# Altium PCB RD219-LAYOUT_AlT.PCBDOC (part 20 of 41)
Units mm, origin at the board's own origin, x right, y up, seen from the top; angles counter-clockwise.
Board outline 209.75 x 159.97 mm, 2 copper layers (TOP, BOTTOM), stack 0 mm thick; 398 components, 199 nets, 1469 pads, 0 vias.
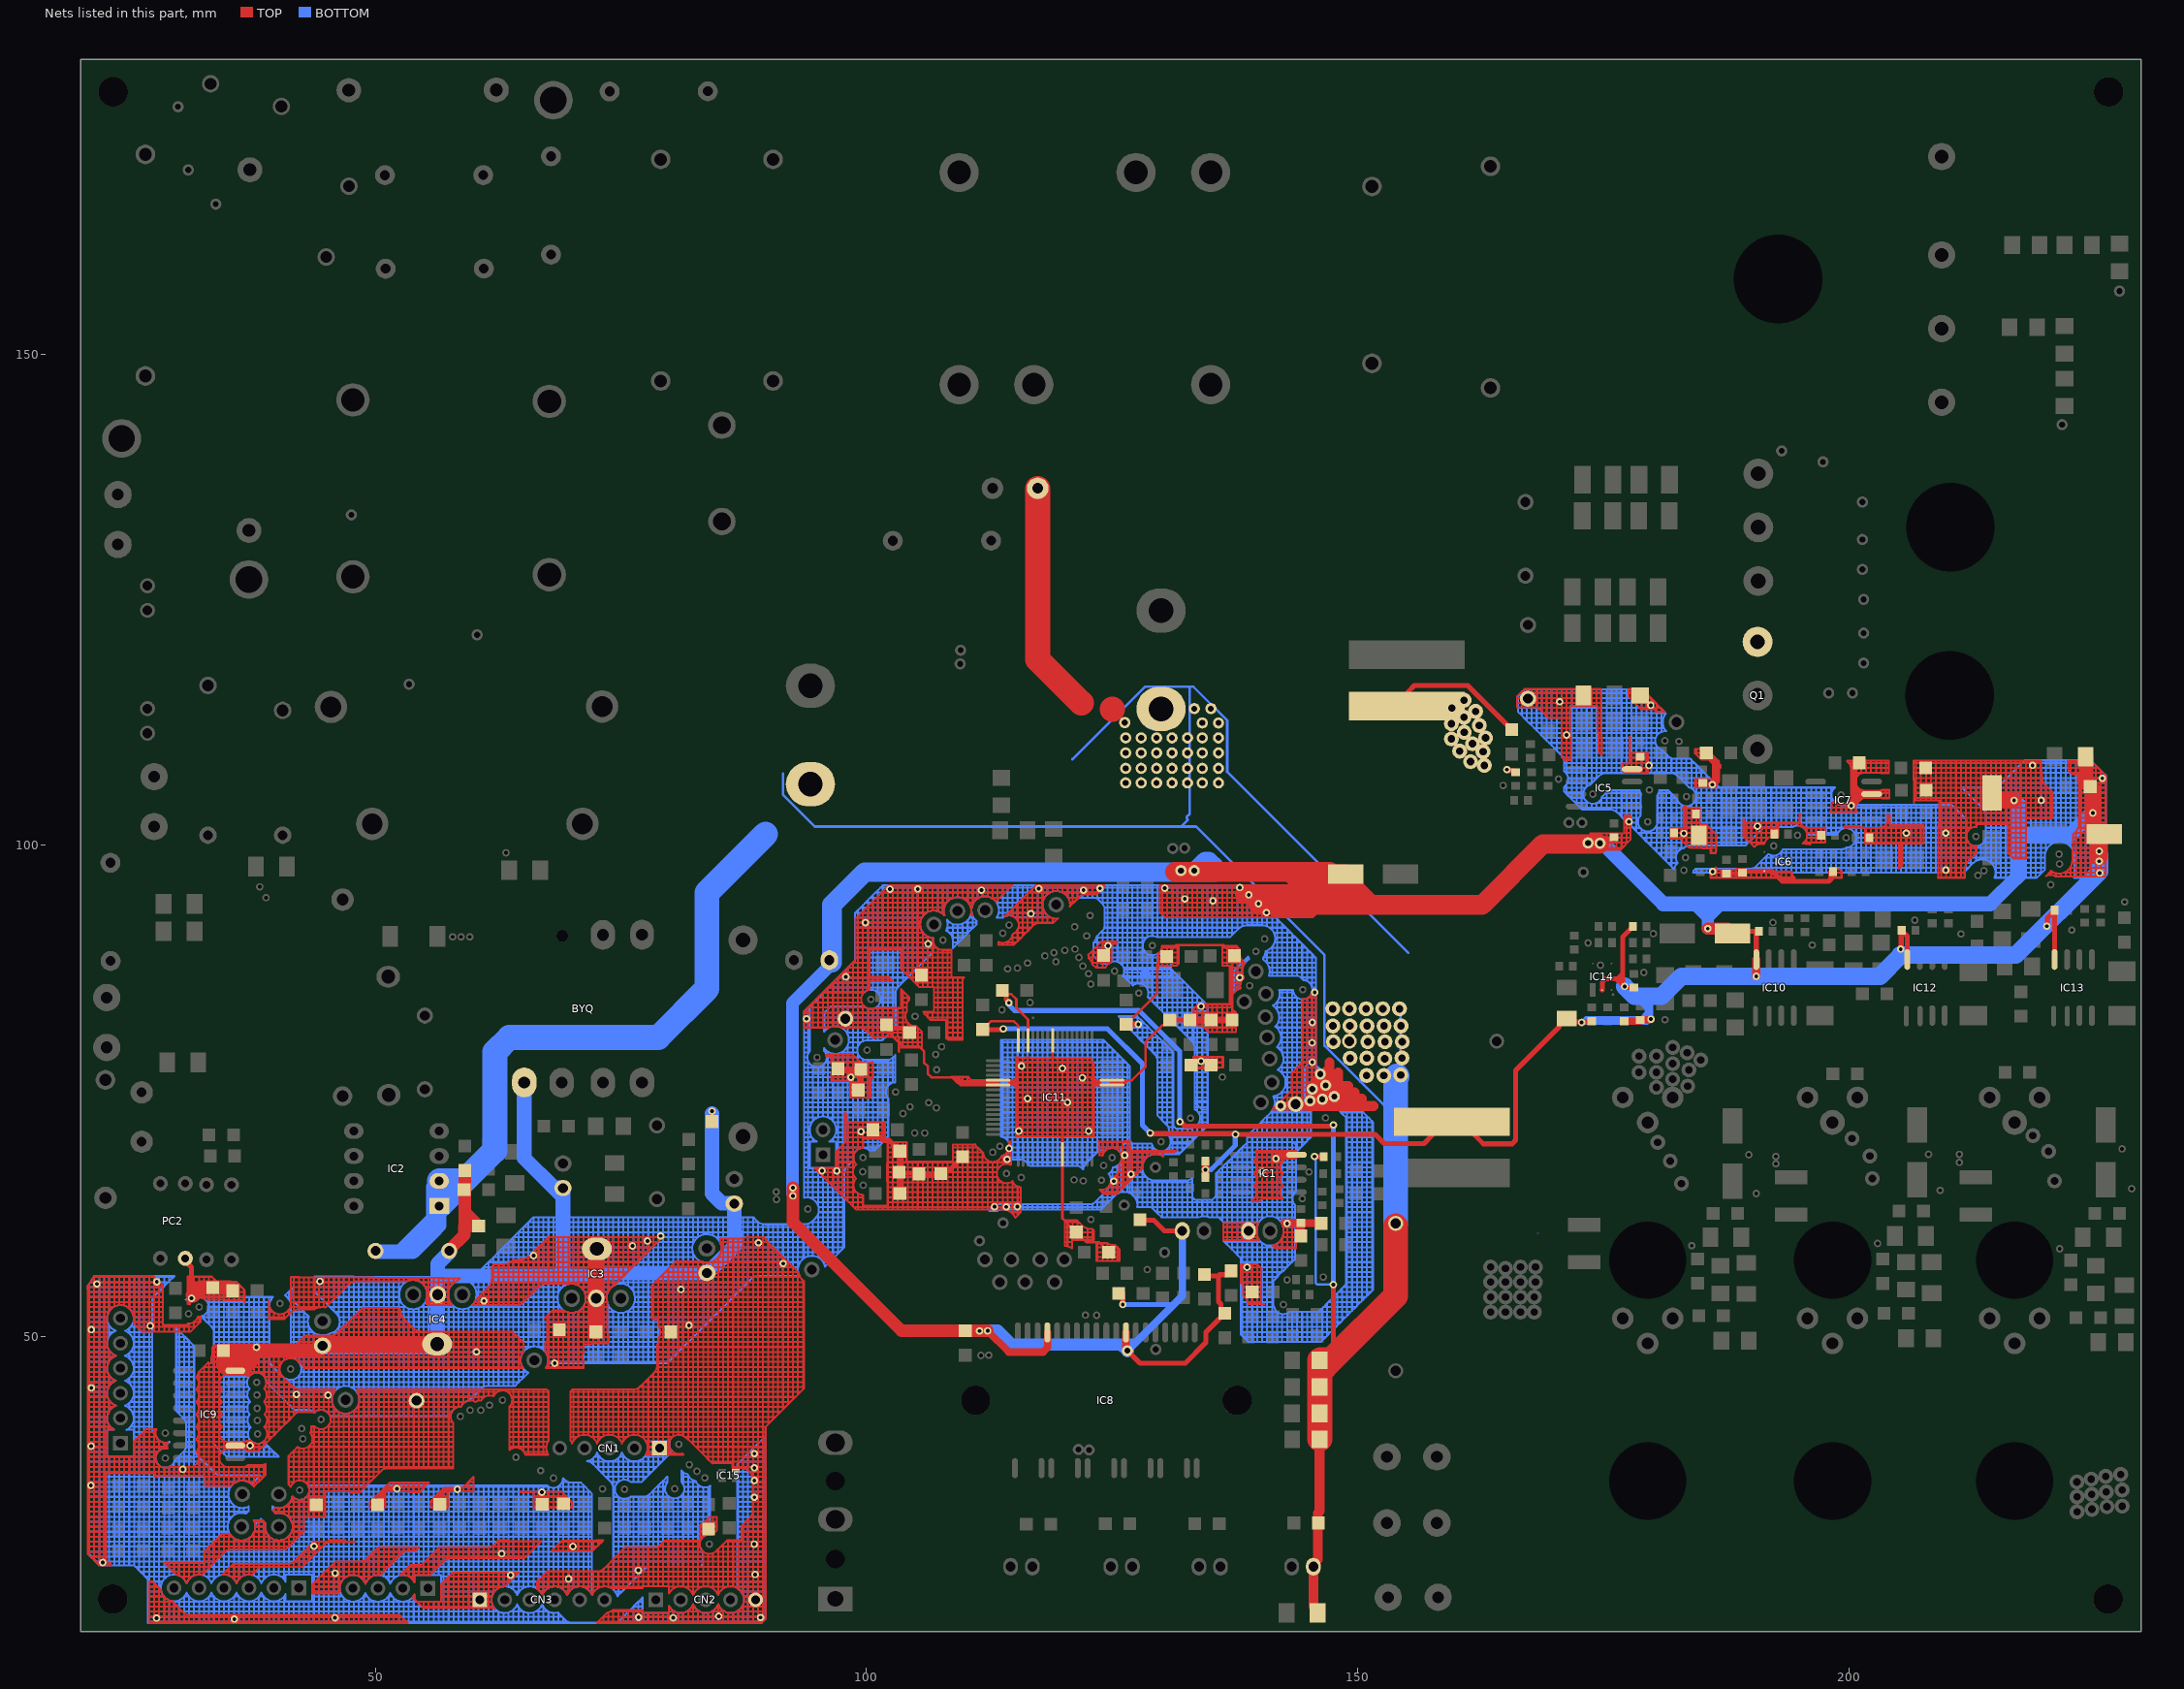
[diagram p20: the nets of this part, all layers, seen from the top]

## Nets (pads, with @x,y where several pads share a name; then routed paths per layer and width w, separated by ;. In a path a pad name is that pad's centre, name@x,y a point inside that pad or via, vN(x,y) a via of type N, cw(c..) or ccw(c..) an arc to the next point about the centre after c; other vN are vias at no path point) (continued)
GND: (continued)
  BOTTOM w0.203: pad.@22.413,27.112 22.921,27.112 ; 22.413,27.62 22.413,28.128 ; 22.413,27.62 22.921,27.62 ; 22.413,28.128 22.413,28.636 ; 22.413,28.128 22.921,28.128 ; 22.413,28.636 22.413,29.144 ; 22.413,28.636 22.921,28.636 ; 22.413,29.144 22.413,29.652 ; 22.413,29.144 22.921,29.144 ; 22.413,29.652 22.413,30.16 ; 22.413,29.652 22.921,29.652 ; 22.413,30.16 22.413,30.668 ; 22.413,30.16 22.921,30.16 ; 22.413,30.668 22.413,31.176 ; 22.413,30.668 22.921,30.668 ; 22.413,31.176 22.413,31.684 ; 22.413,31.176 22.921,31.176 ; 22.413,31.684 22.413,32.192 ; 22.413,31.684 22.921,31.684 ; 22.413,32.192 22.413,32.7 ; 22.413,32.192 22.921,32.192 ; 22.413,32.7 22.413,33.208 ; 22.413,32.7 22.921,32.7 ; 22.413,33.208 22.413,33.716 ; 22.413,33.208 22.921,33.208 ; 22.413,33.716 22.413,34.224 ; 22.413,33.716 22.921,33.716 ; 22.413,34.224 22.413,34.732 ; 22.413,34.224 22.921,34.224 ; 22.413,34.732 22.413,35.24 ; 22.413,34.732 22.921,34.732 ; 22.413,35.24 22.413,35.748 ; 22.413,35.24 22.921,35.24 ; 22.413,35.748 22.413,36.256 ; 22.413,35.748 22.921,35.748 ; 22.413,36.256 22.921,36.256 ; 22.413,36.256 22.413,36.764 ; 22.413,36.764 22.413,37.272 ; 22.413,36.764 22.921,36.764 ; 22.413,37.272 22.413,37.78 ; 22.413,37.272 22.921,37.272 ; 22.413,37.78 22.413,38.288 ; 22.413,37.78 22.921,37.78 ; 22.413,38.288 22.413,38.796 ; 22.413,38.288 22.712,38.288 ; 22.413,38.796 22.413,39.304 ; 22.413,38.796 22.712,38.796 ; 22.413,39.304 22.413,39.812 ; 22.413,39.304 22.712,39.304 ; 22.413,39.812 22.413,40.32 ; 22.413,39.812 22.712,39.812 ; 22.413,40.32 22.413,40.828 ; 22.413,40.32 22.712,40.32 ; 22.413,40.828 22.413,41.336 ; 22.413,40.828 22.921,40.828 ; 22.413,41.336 22.413,41.844 ; 22.413,41.336 22.767,41.336 ; 22.413,41.844 22.413,42.352 ; 22.413,41.844 22.718,41.844 ; 22.413,42.352 22.413,42.86 ; 22.413,42.352 22.871,42.352 ; 22.413,42.86 22.413,43.368 ; 22.413,42.86 22.921,42.86 ; 22.413,43.368 22.413,43.876 ; 22.413,43.368 22.921,43.368 ; 22.413,43.876 22.413,44.384 ; 22.413,43.876 22.767,43.876 ; 22.413,44.384 22.413,44.892 ; 22.413,44.384 22.718,44.384 ; 22.413,44.892 22.413,45.4 ; 22.413,44.892 22.871,44.892 ; 22.413,45.4 22.413,45.908 ; 22.413,45.4 22.921,45.4 ; 22.413,45.908 22.413,46.416 ; 22.413,45.908 22.921,45.908 ; 22.413,46.416 22.413,46.924 ; 22.413,46.416 22.767,46.416 ; 22.413,46.924 22.413,47.432 ; 22.413,46.924 22.718,46.924 ; 22.413,47.432 22.413,47.94 ; 22.413,47.432 22.871,47.432 ; 22.413,47.94 22.413,48.448 ; 22.413,47.94 22.921,47.94 ; 22.413,48.448 22.413,48.956 ; 22.413,48.448 22.921,48.448 ; 22.413,48.956 22.413,49.464 ; 22.413,48.956 22.767,48.956 ; 22.413,49.464 22.413,49.972 ; 22.413,49.464 22.718,49.464 ; 22.413,49.972 22.413,50.48 ; 22.413,49.972 22.871,49.972 ; 22.413,50.48 22.413,50.988 ; 22.413,50.48 22.921,50.48 ; 22.413,50.988 22.413,51.496 ; 22.413,50.988 22.921,50.988 ; 22.413,51.496 22.413,52.004 ; 22.413,51.496 22.767,51.496 ; 22.413,52.004 22.413,52.512 ; 22.413,52.004 22.718,52.004 ; 22.413,52.512 22.413,53.02 ; 22.413,52.512 22.871,52.512 ; 22.413,53.02 22.413,53.528 ; 22.413,53.02 22.921,53.02 ; 22.413,53.528 22.413,54.036 ; 22.413,53.528 22.921,53.528 ; 22.413,54.036 22.413,54.544 ; 22.413,54.036 22.921,54.036 ; 22.413,54.544 22.413,55.052 ; 22.413,54.544 22.921,54.544 ; 22.413,55.052 22.921,55.052 ; 22.413,55.052 22.413,55.56 ; 22.413,55.56 22.413,56.068 ; 22.413,55.56 22.921,55.56 ; 22.413,56.068 22.413,56.192 ; 22.413,56.068 22.921,56.068 ; 22.413,56.192 22.921,56.19 ; 22.712,38.288 22.712,38.796 ; 22.712,38.288 22.712,37.825 22.921,37.825 ; 22.712,38.796 22.712,39.304 ; 22.712,39.304 22.712,39.812 ; 22.712,39.812 22.712,40.32 ; 22.712,40.32 22.712,40.529 22.921,40.529 ; 22.718,41.844 ccw(c24.064,41.717) 22.718,41.835 ccw(c24.064,41.717) 22.767,41.336 ; 22.718,41.844 cw(c24.064,41.717) 22.871,42.352 ; 22.718,44.384 ccw(c24.064,44.257) 22.718,44.375 ccw(c24.064,44.257) 22.767,43.876 ; 22.718,44.384 cw(c24.064,44.257) 22.871,44.892 ; 22.718,46.924 ccw(c24.064,46.797) 22.718,46.915 ccw(c24.064,46.797) 22.767,46.416 ; 22.718,46.924 cw(c24.064,46.797) 22.871,47.432 ; 22.718,49.464 ccw(c24.064,49.337) 22.718,49.455 ccw(c24.064,49.337) 22.767,48.956 ; 22.718,49.464 cw(c24.064,49.337) 22.871,49.972 ; 22.718,52.004 ccw(c24.064,51.877) 22.718,51.995 ccw(c24.064,51.877) 22.767,51.496 ; 22.718,52.004 cw(c24.064,51.877) 22.871,52.512 ; 22.767,41.336 ccw(c24.064,41.717) 22.918,41.001 ccw(c24.064,41.717) 22.921,40.996 ; 22.767,43.876 ccw(c24.064,44.257) 22.918,43.541 ccw(c24.064,44.257) 22.921,43.536 ; 22.767,46.416 ccw(c24.064,46.797) 22.918,46.081 ccw(c24.064,46.797) 22.921,46.076 ; 22.767,48.956 ccw(c24.064,49.337) 22.918,48.621 ccw(c24.064,49.337) 22.921,48.616 ; 22.767,51.496 ccw(c24.064,51.877) 22.918,51.161 ccw(c24.064,51.877) 22.921,51.156 ; 22.871,42.352 cw(c24.064,41.717) 22.918,42.433 cw(c24.064,41.717) 22.921,42.438 ; 22.871,44.892 cw(c24.064,44.257) 22.918,44.973 cw(c24.064,44.257) 22.921,44.978 ; 22.871,47.432 cw(c24.064,46.797) 22.918,47.513 cw(c24.064,46.797) 22.921,47.518 ; 22.871,49.972 cw(c24.064,49.337) 22.918,50.053 cw(c24.064,49.337) 22.921,50.058 ; 22.921,26.731 22.921,27.112 ; 22.921,26.731 23.429,26.731 ; 22.921,27.112 22.921,27.62 ; 22.921,27.112 23.429,27.112 ; 22.921,27.62 22.921,28.128 ; 22.921,27.62 23.429,27.62 ; 22.921,28.128 22.921,28.636 ; 22.921,28.128 23.429,28.128 ; 22.921,28.636 22.921,29.144 ; 22.921,28.636 23.429,28.636 ; 22.921,29.144 22.921,29.652 ; 22.921,29.144 23.429,29.144 ; 22.921,29.652 22.921,30.16 ; 22.921,29.652 23.429,29.652 ; 22.921,30.16 22.921,30.668 ; 22.921,30.16 23.429,30.16 ; 22.921,30.668 22.921,31.176 ; 22.921,30.668 23.429,30.668 ; 22.921,31.176 22.921,31.684 ; 22.921,31.176 23.429,31.176 ; 22.921,31.684 22.921,32.192 ; 22.921,31.684 23.429,31.684 ; 22.921,32.192 22.921,32.7 ; 22.921,32.192 23.429,32.192 ; 22.921,32.7 22.921,33.208 ; 22.921,32.7 23.429,32.7 ; 22.921,33.208 22.921,33.716 ; 22.921,33.208 23.429,33.208 ; 22.921,33.716 22.921,34.224 ; 22.921,33.716 23.429,33.716 ; 22.921,34.224 22.921,34.732 ; 22.921,34.224 23.429,34.224 ; 22.921,34.732 22.921,35.24 ; 22.921,34.732 23.429,34.732 ; 22.921,35.24 22.921,35.748 ; 22.921,35.24 23.429,35.24 ; 22.921,35.748 22.921,36.256 ; 22.921,35.748 23.429,35.748 ; 22.921,36.256 22.921,36.764 ; 22.921,36.256 23.429,36.256 ; 22.921,36.764 22.921,37.272 ; 22.921,36.764 23.429,36.764 ; 22.921,37.272 22.921,37.78 ; 22.921,37.272 23.429,37.272 ; 22.921,37.78 22.921,37.825 ; 22.921,37.78 23.429,37.78 ; 22.921,37.825 23.429,37.825 ; 22.921,40.529 22.921,40.828 ; 22.921,40.828 22.921,40.996 ; 22.921,40.828 23.046,40.828 ; 22.921,40.996 ccw(c24.064,41.717) 23.044,40.83 ccw(c24.064,41.717) 23.046,40.828 ; 22.921,42.438 cw(c24.064,41.717) 23.343,42.86 ; 22.921,42.438 22.921,42.86 ; 22.921,42.86 22.921,43.368 ; 22.921,42.86 23.343,42.86 ; 22.921,43.368 23.046,43.368 ; 22.921,43.368 22.921,43.536 ; 22.921,43.536 ccw(c24.064,44.257) 23.044,43.37 ccw(c24.064,44.257) 23.046,43.368 ; 22.921,44.978 cw(c24.064,44.257) 23.343,45.4 ; 22.921,44.978 22.921,45.4 ; 22.921,45.4 22.921,45.908 ; 22.921,45.4 23.343,45.4 ; 22.921,45.908 22.921,46.076 ; 22.921,45.908 23.046,45.908 ; 22.921,46.076 ccw(c24.064,46.797) 23.044,45.91 ccw(c24.064,46.797) 23.046,45.908 ; 22.921,47.518 cw(c24.064,46.797) 23.343,47.94 ; 22.921,47.518 22.921,47.94 ; 22.921,47.94 22.921,48.448 ; 22.921,47.94 23.343,47.94 ; 22.921,48.448 22.921,48.616 ; 22.921,48.448 23.046,48.448 ; 22.921,48.616 ccw(c24.064,49.337) 23.044,48.45 ccw(c24.064,49.337) 23.046,48.448 ; 22.921,50.058 cw(c24.064,49.337) 23.343,50.48 ; 22.921,50.058 22.921,50.48 ; 22.921,50.48 22.921,50.988 ; 22.921,50.48 23.343,50.48 ; 22.921,50.988 23.046,50.988 ; 22.921,50.988 22.921,51.156 ; 22.921,51.156 ccw(c24.064,51.877) 23.046,50.988 ; 22.921,53.02 22.921,53.528 ; 22.921,53.02 23.343,53.02 ; 22.921,53.528 22.921,54.036 ; 22.921,53.528 23.429,53.528 ; 22.921,54.036 22.921,54.544 ; 22.921,54.036 23.429,54.036 ; 22.921,54.544 22.921,55.052 ; 22.921,54.544 23.429,54.544 ; 22.921,55.052 22.921,55.56 ; 22.921,55.052 23.429,55.052 ; 22.921,55.56 22.921,56.068 ; 22.921,55.56 23.429,55.56 ; 22.921,56.068 22.921,56.19 ; 22.921,56.068 23.429,56.068 ; 22.921,56.19 23.429,56.188 ; 23.046,43.368 ccw(c24.064,44.257) 23.429,43.064 ; 23.046,45.908 ccw(c24.064,46.797) 23.429,45.604 ; 23.046,48.448 ccw(c24.064,49.337) 23.429,48.144 ; 23.046,50.988 ccw(c24.064,51.877) 23.429,50.684 ; 23.343,42.86 cw(c24.064,41.717) 23.429,42.91 ; 23.343,45.4 cw(c24.064,44.257) 23.429,45.45 ; 23.343,47.94 cw(c24.064,46.797) 23.429,47.99 ; 23.343,50.48 cw(c24.064,49.337) 23.429,50.53 ; 23.343,53.02 cw(c24.064,51.877) 23.348,53.023 cw(c24.064,51.877) 23.429,53.07 ; 23.429,26.731 23.429,27.112 ; 23.429,26.731 23.937,26.731 ; 23.429,27.112 23.429,27.62 ; 23.429,27.112 23.937,27.112 ; 23.429,27.62 23.429,28.128 ; 23.429,27.62 23.937,27.62 ; 23.429,28.128 23.429,28.636 ; 23.429,28.128 23.937,28.128 ; 23.429,28.636 23.429,29.144 ; 23.429,28.636 23.937,28.636 ; 23.429,29.144 23.429,29.652 ; 23.429,29.144 23.937,29.144 ; 23.429,29.652 23.429,30.16 ; 23.429,29.652 23.937,29.652 ; 23.429,30.16 23.429,30.668 ; 23.429,30.16 23.937,30.16 ; 23.429,30.668 23.429,31.176 ; 23.429,30.668 23.937,30.668 ; 23.429,31.176 23.429,31.684 ; 23.429,31.176 23.937,31.176 ; 23.429,31.684 23.429,32.192 ; 23.429,31.684 23.937,31.684 ; 23.429,32.192 23.429,32.7 ; 23.429,32.192 23.937,32.192 ; 23.429,32.7 23.429,33.208 ; 23.429,32.7 23.937,32.7 ; 23.429,33.208 23.429,33.716 ; 23.429,33.208 23.937,33.208 ; 23.429,33.716 23.429,34.224 ; 23.429,33.716 23.937,33.716 ; 23.429,34.224 23.429,34.732 ; 23.429,34.224 23.937,34.224 ; 23.429,34.732 23.429,35.24 ; 23.429,34.732 23.937,34.732 ; 23.429,35.24 23.429,35.748 ; 23.429,35.24 23.937,35.24 ; 23.429,35.748 23.429,36.256 ; 23.429,35.748 23.937,35.748 ; 23.429,36.256 23.429,36.764 ; 23.429,36.256 23.937,36.256 ; 23.429,36.764 23.429,37.272 ; 23.429,36.764 23.937,36.764 ; 23.429,37.272 23.429,37.78 ; 23.429,37.272 23.937,37.272 ; 23.429,37.78 23.429,37.825 ; 23.429,37.78 23.937,37.78 ; 23.429,37.825 23.937,37.825 ; 23.429,42.91 cw(c24.064,41.717) 23.601,42.987 cw(c24.064,44.257) 23.429,43.064 ; 23.429,42.91 23.429,43.064 ; 23.429,45.45 cw(c24.064,44.257) 23.601,45.527 cw(c24.064,46.797) 23.429,45.604 ; 23.429,45.45 23.429,45.604 ; 23.429,47.99 cw(c24.064,46.797) 23.601,48.067 cw(c24.064,49.337) 23.429,48.144 ; 23.429,47.99 23.429,48.144 ; 23.429,50.53 cw(c24.064,49.337) 23.601,50.607 cw(c24.064,51.877) 23.429,50.684 ; 23.429,50.53 23.429,50.684 ; 23.429,53.07 cw(c24.064,51.877) 23.937,53.223 ; 23.429,53.07 23.429,53.528 ; 23.429,53.528 23.429,54.036 ; 23.429,53.528 23.937,53.528 ; 23.429,54.036 23.429,54.544 ; 23.429,54.036 23.937,54.036 ; 23.429,54.544 23.429,55.052 ; 23.429,54.544 23.937,54.544 ; 23.429,55.052 23.429,55.56 ; 23.429,55.052 23.937,55.052 ; 23.429,55.56 23.429,56.068 ; 23.429,55.56 23.937,55.56 ; 23.429,56.068 23.429,56.188 ; 23.429,56.068 23.937,56.068 ; 23.429,56.188 23.937,56.187 ; 23.937,26.731 23.937,27.112 ; 23.937,26.731 24.445,26.731 ; 23.937,27.112 23.937,27.62 ; 23.937,27.112 24.445,27.112 ; 23.937,27.62 23.937,28.128 ; 23.937,27.62 24.445,27.62 ; 23.937,28.128 23.937,28.636 ; 23.937,28.128 24.445,28.128 ; 23.937,28.636 23.937,29.144 ; 23.937,28.636 24.445,28.636 ; 23.937,29.144 23.937,29.652 ; 23.937,29.144 24.445,29.144 ; 23.937,29.652 23.937,30.16 ; 23.937,29.652 24.445,29.652 ; 23.937,30.16 23.937,30.668 ; 23.937,30.16 24.445,30.16 ; 23.937,30.668 23.937,31.176 ; 23.937,30.668 24.445,30.668 ; 23.937,31.176 23.937,31.684 ; 23.937,31.176 24.445,31.176 ; 23.937,31.684 23.937,32.192 ; 23.937,31.684 24.445,31.684 ; 23.937,32.192 23.937,32.7 ; 23.937,32.192 24.445,32.192 ; 23.937,32.7 23.937,33.208 ; 23.937,32.7 24.445,32.7 ; 23.937,33.208 23.937,33.716 ; 23.937,33.208 24.445,33.208 ; 23.937,33.716 23.937,34.224 ; 23.937,33.716 24.445,33.716 ; 23.937,34.224 23.937,34.732 ; 23.937,34.224 24.445,34.224 ; 23.937,34.732 23.937,35.24 ; 23.937,34.732 24.445,34.732 ; 23.937,35.24 23.937,35.748 ; 23.937,35.24 24.445,35.24 ; 23.937,35.748 23.937,36.256 ; 23.937,35.748 24.445,35.748 ; 23.937,36.256 23.937,36.764 ; 23.937,36.256 24.445,36.256 ; 23.937,36.764 23.937,37.272 ; 23.937,36.764 24.445,36.764 ; 23.937,37.272 23.937,37.78 ; 23.937,37.272 24.445,37.272 ; 23.937,37.78 23.937,37.825 ; 23.937,37.78 24.445,37.78 ; 23.937,37.825 24.445,37.825 ; 23.937,53.223 cw(c24.064,51.877) 24.437,53.176 cw(c24.064,51.877) 24.445,53.174 ; 23.937,53.223 23.937,53.528 ; 23.937,53.528 23.937,54.036 ; 23.937,53.528 24.445,53.528 ; 23.937,54.036 23.937,54.544 ; 23.937,54.036 24.445,54.036 ; 23.937,54.544 23.937,55.052 ; 23.937,54.544 24.445,54.544 ; 23.937,55.052 23.937,55.56 ; 23.937,55.052 24.445,55.052 ; 23.937,55.56 23.937,56.068 ; 23.937,55.56 24.445,55.56 ; 23.937,56.068 23.937,56.187 ; 23.937,56.068 24.445,56.068 ; 23.937,56.187 24.445,56.185 ; 24.445,26.731 24.445,27.112 ; 24.445,26.731 24.953,26.731 ; 24.445,27.112 24.445,27.62 ; 24.445,27.112 24.953,27.112 ; 24.445,27.62 24.445,28.128 ; 24.445,27.62 24.953,27.62 ; 24.445,28.128 24.445,28.636 ; 24.445,28.128 24.953,28.128 ; 24.445,28.636 24.445,29.144 ; 24.445,28.636 24.953,28.636 ; 24.445,29.144 24.445,29.652 ; 24.445,29.144 24.953,29.144 ; 24.445,29.652 24.445,30.16 ; 24.445,29.652 24.953,29.652 ; 24.445,30.16 24.445,30.668 ; 24.445,30.16 24.953,30.16 ; 24.445,30.668 24.445,31.176 ; 24.445,30.668 24.953,30.668 ; 24.445,31.176 24.445,31.684 ; 24.445,31.176 24.953,31.176 ; 24.445,31.684 24.445,32.192 ; 24.445,31.684 24.953,31.684 ; 24.445,32.192 24.445,32.7 ; 24.445,32.192 24.953,32.192 ; 24.445,32.7 24.445,33.208 ; 24.445,32.7 24.953,32.7 ; 24.445,33.208 24.445,33.716 ; 24.445,33.208 24.953,33.208 ; 24.445,33.716 24.445,34.224 ; 24.445,33.716 24.953,33.716 ; 24.445,34.224 24.445,34.732 ; 24.445,34.224 24.953,34.224 ; 24.445,34.732 24.445,35.24 ; 24.445,34.732 24.953,34.732 ; 24.445,35.24 24.445,35.748 ; 24.445,35.24 24.953,35.24 ; 24.445,35.748 24.445,36.256 ; 24.445,35.748 24.953,35.748 ; 24.445,36.256 24.445,36.764 ; 24.445,36.256 24.953,36.256 ; 24.445,36.764 24.445,37.272 ; 24.445,36.764 24.953,36.764 ; 24.445,37.272 24.445,37.78 ; 24.445,37.272 24.953,37.272 ; 24.445,37.78 24.445,37.825 ; 24.445,37.78 24.953,37.78 ; 24.445,37.825 24.953,37.825 ; 24.445,53.174 cw(c24.064,51.877) 24.78,53.023 cw(c24.064,51.877) 24.785,53.02 ; 24.445,53.174 24.445,53.528 ; 24.445,53.528 24.445,54.036 ; 24.445,53.528 24.953,53.528 ; 24.445,54.036 24.445,54.544 ; 24.445,54.036 24.953,54.036 ; 24.445,54.544 24.445,55.052 ; 24.445,54.544 24.953,54.544 ; 24.445,55.052 24.445,55.56 ; 24.445,55.052 24.953,55.052 ; 24.445,55.56 24.445,56.068 ; 24.445,55.56 24.953,55.56 ; 24.445,56.068 24.445,56.185 ; 24.445,56.068 24.953,56.068 ; 24.445,56.185 24.953,56.183 ; 24.708,40.529 ccw(c24.064,41.717) 24.953,40.699 ; 24.708,40.529 24.953,40.529 ; 24.785,42.86 ccw(c24.064,41.717) 24.78,42.863 ccw(c24.064,41.717) 24.527,42.987 ccw(c24.064,44.257) 24.953,43.239 ; 24.785,42.86 cw(c24.064,41.717) 24.951,42.737 cw(c24.064,41.717) 24.953,42.735 ; 24.785,42.86 24.953,42.86 ; 24.785,45.4 cw(c24.064,44.257) 24.951,45.277 cw(c24.064,44.257) 24.953,45.275 ; 24.785,45.4 ccw(c24.064,44.257) 24.78,45.403 ccw(c24.064,44.257) 24.527,45.527 ccw(c24.064,46.797) 24.951,45.777 ccw(c24.064,46.797) 24.953,45.779 ; 24.785,45.4 24.953,45.4 ; 24.785,47.94 cw(c24.064,46.797) 24.951,47.817 cw(c24.064,46.797) 24.953,47.815 ; 24.785,47.94 ccw(c24.064,46.797) 24.78,47.943 ccw(c24.064,46.797) 24.527,48.067 ccw(c24.064,49.337) 24.953,48.319 ; 24.785,47.94 24.953,47.94 ; 24.785,50.48 cw(c24.064,49.337) 24.951,50.357 cw(c24.064,49.337) 24.953,50.355 ; 24.785,50.48 ccw(c24.064,49.337) 24.78,50.483 ccw(c24.064,49.337) 24.527,50.607 ccw(c24.064,51.877) 24.953,50.859 ; 24.785,50.48 24.953,50.48 ; 24.785,53.02 cw(c24.064,51.877) 24.951,52.897 cw(c24.064,51.877) 24.953,52.895 ; 24.785,53.02 24.953,53.02 ; 24.953,26.731 25.461,26.731 ; 24.953,26.731 24.953,27.112 ; 24.953,27.112 24.953,27.62 ; 24.953,27.112 25.461,27.112 ; 24.953,27.62 24.953,28.128 ; 24.953,27.62 25.461,27.62 ; 24.953,28.128 24.953,28.636 ; 24.953,28.128 25.461,28.128 ; 24.953,28.636 24.953,29.144 ; 24.953,28.636 25.461,28.636 ; 24.953,29.144 24.953,29.652 ; 24.953,29.144 25.461,29.144 ; 24.953,29.652 24.953,30.16 ; 24.953,29.652 25.461,29.652 ; 24.953,30.16 24.953,30.668 ; 24.953,30.16 25.461,30.16 ; 24.953,30.668 24.953,31.176 ; 24.953,30.668 25.461,30.668 ; 24.953,31.176 24.953,31.684 ; 24.953,31.176 25.461,31.176 ; 24.953,31.684 24.953,32.192 ; 24.953,31.684 25.461,31.684 ; 24.953,32.192 25.461,32.192 ; 24.953,32.192 24.953,32.7 ; 24.953,32.7 24.953,33.208 ; 24.953,32.7 25.461,32.7 ; 24.953,33.208 24.953,33.716 ; 24.953,33.208 25.461,33.208 ; 24.953,33.716 24.953,34.224 ; 24.953,33.716 25.461,33.716 ; 24.953,34.224 24.953,34.732 ; 24.953,34.224 25.461,34.224 ; 24.953,34.732 25.461,34.732 ; 24.953,34.732 24.953,35.24 ; 24.953,35.24 25.461,35.24 ; 24.953,35.24 24.953,35.748 ; 24.953,35.748 25.461,35.748 ; 24.953,35.748 24.953,36.256 ; 24.953,36.256 25.461,36.256 ; 24.953,36.256 24.953,36.764 ; 24.953,36.764 24.953,37.272 ; 24.953,36.764 25.461,36.764 ; 24.953,37.272 24.953,37.78 ; 24.953,37.272 25.461,37.272 ; 24.953,37.78 24.953,37.825 ; 24.953,37.78 25.461,37.78 ; 24.953,37.825 25.416,37.825 25.416,38.288 ; 24.953,40.529 25.416,40.529 25.416,40.32 ; 24.953,40.529 24.953,40.699 ; 24.953,42.735 cw(c24.064,41.717) 25.257,42.352 ; 24.953,42.735 24.953,42.86 ; 24.953,42.86 25.461,42.86 ; 24.953,42.86 24.953,43.239 ; 24.953,43.239 ccw(c24.064,44.257) 25.082,43.368 ; 24.953,45.275 cw(c24.064,44.257) 25.257,44.892 ; 24.953,45.275 24.953,45.4 ; 24.953,45.4 25.461,45.4 ; 24.953,45.4 24.953,45.779 ; 24.953,45.779 ccw(c24.064,46.797) 25.082,45.908 ; 24.953,47.815 cw(c24.064,46.797) 25.257,47.432 ; 24.953,47.815 24.953,47.94 ; 24.953,47.94 25.461,47.94 ; 24.953,47.94 24.953,48.319 ; 24.953,48.319 ccw(c24.064,49.337) 25.082,48.448 ; 24.953,50.355 cw(c24.064,49.337) 25.257,49.972 ; 24.953,50.355 24.953,50.48 ; 24.953,50.48 25.461,50.48 ; 24.953,50.48 24.953,50.859 ; 24.953,50.859 ccw(c24.064,51.877) 25.082,50.988 ; 24.953,52.895 cw(c24.064,51.877) 25.257,52.512 ; 24.953,52.895 24.953,53.02 ; 24.953,53.02 24.953,53.528 ; 24.953,53.02 25.461,53.02 ; 24.953,53.528 25.461,53.528 ; 24.953,53.528 24.953,54.036 ; 24.953,54.036 25.461,54.036 ; 24.953,54.036 24.953,54.544 ; 24.953,54.544 24.953,55.052 ; 24.953,54.544 25.461,54.544 ; 24.953,55.052 25.461,55.052 ; 24.953,55.052 24.953,55.56 ; 24.953,55.56 24.953,56.068 ; 24.953,55.56 25.461,55.56 ; 24.953,56.068 25.461,56.068 ; 24.953,56.068 24.953,56.183 ; 24.953,56.183 25.461,56.182 ; 25.082,43.368 ccw(c24.064,44.257) 25.084,43.37 ccw(c24.064,44.257) 25.361,43.876 ; 25.082,43.368 25.461,43.368 ; 25.082,45.908 25.461,45.908 ; 25.082,48.448 ccw(c24.064,49.337) 25.084,48.45 ccw(c24.064,49.337) 25.361,48.956 ; 25.082,48.448 25.461,48.448 ; 25.082,50.988 ccw(c24.064,51.877) 25.084,50.99 ccw(c24.064,51.877) 25.361,51.496 ; 25.082,50.988 25.461,50.988 ; 25.257,42.352 cw(c24.064,41.717) 25.41,41.844 ; 25.257,42.352 25.461,42.352 ; 25.257,44.892 cw(c24.064,44.257) 25.41,44.384 ; 25.257,44.892 25.461,44.892 ; 25.257,47.432 cw(c24.064,46.797) 25.41,46.924 ; 25.257,47.432 25.461,47.432 ; 25.257,49.972 cw(c24.064,49.337) 25.41,49.464 ; 25.257,49.972 25.461,49.972 ; 25.257,52.512 cw(c24.064,51.877) 25.41,52.004 ; 25.257,52.512 25.461,52.512 ; 25.361,41.336 ccw(c24.064,41.717) 25.363,41.344 ccw(c24.064,41.717) 25.416,41.717 ccw(c24.064,41.717) 25.41,41.844 ; 25.361,41.336 25.461,41.336 ; 25.361,43.876 ccw(c24.064,44.257) 25.363,43.884 ccw(c24.064,44.257) 25.416,44.257 ccw(c24.064,44.257) 25.41,44.384 ; 25.361,43.876 25.461,43.876 ; 25.361,48.956 ccw(c24.064,49.337) 25.363,48.964 ccw(c24.064,49.337) 25.416,49.337 ccw(c24.064,49.337) 25.41,49.464 ; 25.361,48.956 25.461,48.956 ; 25.361,51.496 ccw(c24.064,51.877) 25.363,51.504 ccw(c24.064,51.877) 25.416,51.877 ccw(c24.064,51.877) 25.41,52.004 ; 25.361,51.496 25.461,51.496 ; 25.41,41.844 25.461,41.844 ; 25.41,44.384 25.461,44.384 ; 25.41,46.924 25.461,46.924 ; 25.41,49.464 25.461,49.464 ; 25.41,52.004 25.461,52.004 ; 25.416,38.288 25.461,38.288 ; 25.416,38.288 25.416,38.796 ; 25.416,38.796 25.461,38.796 ; 25.416,38.796 25.416,39.304 ; 25.416,39.304 25.461,39.304 ; 25.416,39.304 25.416,39.812 ; 25.416,39.812 25.461,39.812 ; 25.416,39.812 25.416,40.32 ; 25.416,40.32 25.461,40.32 ; 25.461,26.731 25.588,26.604 ; 25.461,26.731 25.461,27.112 ; 25.461,27.112 25.461,27.62 ; 25.461,27.112 25.969,27.112 ; 25.461,27.62 25.461,28.128 ; 25.461,27.62 25.969,27.62 ; 25.461,28.128 25.461,28.636 ; 25.461,28.128 25.969,28.128 ; 25.461,28.636 25.461,29.144 ; 25.461,28.636 25.969,28.636 ; 25.461,29.144 25.461,29.652 ; 25.461,29.144 25.969,29.144 ; 25.461,29.652 25.461,30.16 ; 25.461,29.652 25.969,29.652 ; 25.461,30.16 25.461,30.668 ; 25.461,30.16 25.969,30.16 ; 25.461,30.668 25.461,31.176 ; 25.461,30.668 25.969,30.668 ; 25.461,31.176 25.461,31.684 ; 25.461,31.176 25.969,31.176 ; 25.461,31.684 25.461,32.192 ; 25.461,31.684 25.969,31.684 ; 25.461,32.192 25.969,32.192 ; 25.461,32.192 25.461,32.7 ; 25.461,32.7 25.461,33.208 ; 25.461,32.7 25.969,32.7 ; 25.461,33.208 25.461,33.716 ; 25.461,33.208 25.969,33.208 ; 25.461,33.716 25.461,34.224 ; 25.461,33.716 25.969,33.716 ; 25.461,34.224 25.461,34.732 ; 25.461,34.224 25.969,34.224 ; 25.461,34.732 25.969,34.732 ; 25.461,34.732 25.461,35.24 ; 25.461,35.24 25.969,35.24 ; 25.461,35.24 25.461,35.748 ; 25.461,35.748 25.969,35.748 ; 25.461,35.748 25.461,36.256 ; 25.461,36.256 25.969,36.256 ; 25.461,36.256 25.461,36.764 ; 25.461,36.764 25.461,37.272 ; 25.461,36.764 25.969,36.764 ; 25.461,37.272 25.461,37.78 ; 25.461,37.272 25.969,37.272 ; 25.461,37.78 25.461,38.288 ; 25.461,37.78 25.969,37.78 ; 25.461,38.288 25.461,38.796 ; 25.461,38.288 25.969,38.288 ; 25.461,38.796 25.969,38.796 ; 25.461,38.796 25.461,39.304 ; 25.461,39.304 25.461,39.812 ; 25.461,39.304 25.969,39.304 ; 25.461,39.812 25.969,39.812 ; 25.461,39.812 25.461,40.32 ; 25.461,40.32 25.461,40.828 ; 25.461,40.32 25.969,40.32 ; 25.461,40.828 25.969,40.828 ; 25.461,40.828 25.461,41.336 ; 25.461,41.336 25.461,41.844 ; 25.461,41.336 25.969,41.336 ; 25.461,41.844 25.969,41.844 ; 25.461,41.844 25.461,42.352 ; 25.461,42.352 25.461,42.86 ; 25.461,42.352 25.969,42.352 ; 25.461,42.86 25.461,43.368 ; 25.461,42.86 25.969,42.86 ; 25.461,43.368 25.461,43.876 ; 25.461,43.368 25.969,43.368 ; 25.461,43.876 25.461,44.384 ; 25.461,43.876 25.969,43.876 ; 25.461,44.384 25.461,44.892 ; 25.461,44.384 25.969,44.384 ; 25.461,44.892 25.461,45.4 ; 25.461,44.892 25.969,44.892 ; 25.461,45.4 25.461,45.908 ; 25.461,45.4 25.969,45.4 ; 25.461,45.908 25.461,46.416 ; 25.461,45.908 25.969,45.908 ; 25.461,46.416 25.461,46.924 ; 25.461,46.416 25.969,46.416 ; 25.461,46.924 25.969,46.924 ; 25.461,46.924 25.461,47.432 ; 25.461,47.432 25.461,47.94 ; 25.461,47.432 25.969,47.432 ; 25.461,47.94 25.461,48.448 ; 25.461,47.94 25.969,47.94 ; 25.461,48.448 25.461,48.956 ; 25.461,48.448 25.969,48.448 ; 25.461,48.956 25.461,49.464 ; 25.461,48.956 25.969,48.956 ; 25.461,49.464 25.461,49.972 ; 25.461,49.464 25.969,49.464 ; 25.461,49.972 25.461,50.48 ; 25.461,49.972 25.969,49.972 ; 25.461,50.48 25.461,50.988 ; 25.461,50.48 25.969,50.48 ; 25.461,50.988 25.461,51.496 ; 25.461,50.988 25.969,50.988 ; 25.461,51.496 25.461,52.004 ; 25.461,51.496 25.969,51.496 ; 25.461,52.004 25.461,52.512 ; 25.461,52.004 25.969,52.004 ; 25.461,52.512 25.461,53.02 ; 25.461,52.512 25.969,52.512 ; 25.461,53.02 25.461,53.528 ; 25.461,53.02 25.969,53.02 ; 25.461,53.528 25.969,53.528 ; 25.461,53.528 25.461,54.036 ; 25.461,54.036 25.969,54.036 ; 25.461,54.036 25.461,54.544 ; 25.461,54.544 25.461,55.052 ; 25.461,54.544 25.969,54.544 ; 25.461,55.052 25.461,55.56 ; 25.461,55.052 25.969,55.052 ; 25.461,55.56 25.461,56.068 ; 25.461,55.56 25.969,55.56 ; 25.461,56.068 25.461,56.182 ; 25.461,56.068 25.969,56.068 ; 25.461,56.182 25.969,56.18 ; 25.588,26.604 25.969,26.223 ; 25.588,26.604 25.969,26.604 ; 25.969,26.223 26.096,26.096 ; 25.969,26.223 25.969,26.604 ; 25.969,26.604 25.969,27.112 ; 25.969,26.604 26.477,26.604 ; 25.969,27.112 25.969,27.62 ; 25.969,27.112 26.477,27.112 ; 25.969,27.62 25.969,28.128 ; 25.969,27.62 26.477,27.62 ; 25.969,28.128 25.969,28.636 ; 25.969,28.128 26.477,28.128 ; 25.969,28.636 25.969,29.144 ; 25.969,28.636 26.477,28.636 ; 25.969,29.144 25.969,29.652 ; 25.969,29.144 26.477,29.144 ; 25.969,29.652 25.969,30.16 ; 25.969,29.652 26.477,29.652 ; 25.969,30.16 25.969,30.668 ; 25.969,30.16 26.477,30.16 ; 25.969,30.668 25.969,31.176 ; 25.969,30.668 26.477,30.668 ; 25.969,31.176 25.969,31.684 ; 25.969,31.176 26.477,31.176 ; 25.969,31.684 25.969,32.192 ; 25.969,31.684 26.477,31.684 ; 25.969,32.192 25.969,32.7 ; 25.969,32.192 26.477,32.192 ; 25.969,32.7 25.969,33.208 ; 25.969,32.7 26.477,32.7 ; 25.969,33.208 25.969,33.716 ; 25.969,33.208 26.477,33.208 ; 25.969,33.716 25.969,34.224 ; 25.969,33.716 26.477,33.716 ; 25.969,34.224 25.969,34.732 ; 25.969,34.224 26.477,34.224 ; 25.969,34.732 25.969,35.24 ; 25.969,34.732 26.477,34.732 ; 25.969,35.24 25.969,35.748 ; 25.969,35.24 26.477,35.24 ; 25.969,35.748 25.969,36.256 ; 25.969,35.748 26.477,35.748 ; 25.969,36.256 25.969,36.764 ; 25.969,36.256 26.477,36.256 ; 25.969,36.764 25.969,37.272 ; 25.969,36.764 26.477,36.764 ; 25.969,37.272 25.969,37.78 ; 25.969,37.272 26.477,37.272 ; 25.969,37.78 25.969,38.288 ; 25.969,37.78 26.477,37.78 ; 25.969,38.288 25.969,38.796 ; 25.969,38.288 26.477,38.288 ; 25.969,38.796 25.969,39.304 ; 25.969,38.796 26.477,38.796 ; 25.969,39.304 25.969,39.812 ; 25.969,39.304 26.477,39.304 ; 25.969,39.812 25.969,40.32 ; 25.969,39.812 26.477,39.812 ; 25.969,40.32 25.969,40.828 ; 25.969,40.32 26.477,40.32 ; 25.969,40.828 25.969,41.336 ; 25.969,40.828 26.477,40.828 ; 25.969,41.336 25.969,41.844 ; 25.969,41.336 26.477,41.336 ; 25.969,41.844 25.969,42.352 ; 25.969,41.844 26.477,41.844 ; 25.969,42.352 25.969,42.86 ; 25.969,42.352 26.477,42.352 ; 25.969,42.86 25.969,43.368 ; 25.969,42.86 26.477,42.86 ; 25.969,43.368 25.969,43.876 ; 25.969,43.368 26.477,43.368 ; 25.969,43.876 25.969,44.384 ; 25.969,43.876 26.477,43.876 ; 25.969,44.384 25.969,44.892 ; 25.969,44.384 26.477,44.384 ; 25.969,44.892 25.969,45.4 ; 25.969,44.892 26.477,44.892 ; 25.969,45.4 25.969,45.908 ; 25.969,45.4 26.477,45.4 ; 25.969,45.908 25.969,46.416 ; 25.969,45.908 26.477,45.908 ; 25.969,46.416 25.969,46.924 ; 25.969,46.416 26.477,46.416 ; 25.969,46.924 25.969,47.432 ; 25.969,46.924 26.477,46.924 ; 25.969,47.432 25.969,47.94 ; 25.969,47.432 26.477,47.432 ; 25.969,47.94 25.969,48.448 ; 25.969,47.94 26.477,47.94 ; 25.969,48.448 25.969,48.956 ; 25.969,48.448 26.477,48.448 ; 25.969,48.956 25.969,49.464 ; 25.969,48.956 26.477,48.956 ; 25.969,49.464 25.969,49.972 ; 25.969,49.464 26.477,49.464 ; 25.969,49.972 25.969,50.48 ; 25.969,49.972 26.477,49.972 ; 25.969,50.48 25.969,50.988 ; 25.969,50.48 26.477,50.48 ; 25.969,50.988 25.969,51.496 ; 25.969,50.988 26.477,50.988 ; 25.969,51.496 25.969,52.004 ; 25.969,51.496 26.477,51.496 ; 25.969,52.004 25.969,52.512 ; 25.969,52.004 26.477,52.004 ; 25.969,52.512 25.969,53.02 ; 25.969,52.512 26.477,52.512 ; 25.969,53.02 25.969,53.528 ; 25.969,53.02 26.477,53.02 ; 25.969,53.528 25.969,54.036 ; 25.969,53.528 26.477,53.528 ; 25.969,54.036 25.969,54.544 ; 25.969,54.036 26.477,54.036 ; 25.969,54.544 25.969,55.052 ; 25.969,54.544 26.477,54.544 ; 25.969,55.052 25.969,55.56 ; 25.969,55.052 26.477,55.052 ; 25.969,55.56 25.969,56.068 ; 25.969,55.56 26.477,55.56 ; 25.969,56.068 25.969,56.18 ; 25.969,56.068 26.477,56.068 ; 25.969,56.18 26.477,56.178 ; 26.096,26.096 26.477,25.715 ; 26.096,26.096 26.477,26.096 ; 26.477,25.715 26.604,25.588 ; 26.477,25.715 26.477,26.096 ; 26.477,26.096 26.477,26.604 ; 26.477,26.096 26.985,26.096 ; 26.477,26.604 26.985,26.604 ; 26.477,26.604 26.477,27.112 ; 26.477,27.112 26.477,27.62 ; 26.477,27.112 26.985,27.112 ; 26.477,27.62 26.477,28.128 ; 26.477,27.62 26.985,27.62 ; 26.477,28.128 26.477,28.636 ; 26.477,28.128 26.985,28.128 ; 26.477,28.636 26.477,29.144 ; 26.477,28.636 26.985,28.636 ; 26.477,29.144 26.477,29.652 ; 26.477,29.144 26.985,29.144 ; 26.477,29.652 26.477,30.16 ; 26.477,29.652 26.985,29.652 ; 26.477,30.16 26.477,30.668 ; 26.477,30.16 26.985,30.16 ; 26.477,30.668 26.477,31.176 ; 26.477,30.668 26.985,30.668 ; 26.477,31.176 26.477,31.684 ; 26.477,31.176 26.985,31.176 ; 26.477,31.684 26.477,32.192 ; 26.477,31.684 26.985,31.684 ; 26.477,32.192 26.985,32.192 ; 26.477,32.192 26.477,32.7 ; 26.477,32.7 26.477,33.208 ; 26.477,32.7 26.985,32.7 ; 26.477,33.208 26.477,33.716 ; 26.477,33.208 26.985,33.208 ; 26.477,33.716 26.477,34.224 ; 26.477,33.716 26.985,33.716 ; 26.477,34.224 26.477,34.732 ; 26.477,34.224 26.985,34.224 ; 26.477,34.732 26.985,34.732 ; 26.477,34.732 26.477,35.24 ; 26.477,35.24 26.985,35.24 ; 26.477,35.24 26.477,35.748 ; 26.477,35.748 26.985,35.748 ; 26.477,35.748 26.477,36.256 ; 26.477,36.256 26.985,36.256 ; 26.477,36.256 26.477,36.764 ; 26.477,36.764 26.477,37.272 ; 26.477,36.764 26.985,36.764 ; 26.477,37.272 26.477,37.78 ; 26.477,37.272 26.985,37.272 ; 26.477,37.78 26.477,38.288 ; 26.477,37.78 26.985,37.78 ; 26.477,38.288 26.477,38.796 ; 26.477,38.288 26.985,38.288 ; 26.477,38.796 26.985,38.796 ; 26.477,38.796 26.477,39.304 ; 26.477,39.304 26.477,39.812 ; 26.477,39.304 26.985,39.304 ; 26.477,39.812 26.985,39.812 ; 26.477,39.812 26.477,40.32 ; 26.477,40.32 26.477,40.828 ; 26.477,40.32 26.985,40.32 ; 26.477,40.828 26.985,40.828 ; 26.477,40.828 26.477,41.336 ; 26.477,41.336 26.477,41.844 ; 26.477,41.336 26.985,41.336 ; 26.477,41.844 26.477,42.352 ; 26.477,41.844 26.985,41.844 ; 26.477,42.352 26.477,42.86 ; 26.477,42.352 26.985,42.352 ; 26.477,42.86 26.477,43.368 ; 26.477,42.86 26.985,42.86 ; 26.477,43.368 26.477,43.876 ; 26.477,43.368 26.985,43.368 ; 26.477,43.876 26.477,44.384 ; 26.477,43.876 26.985,43.876 ; 26.477,44.384 26.477,44.892 ; 26.477,44.384 26.985,44.384 ; 26.477,44.892 26.477,45.4 ; 26.477,44.892 26.985,44.892 ; 26.477,45.4 26.477,45.908 ; 26.477,45.4 26.985,45.4 ; 26.477,45.908 26.477,46.416 ; 26.477,45.908 26.985,45.908 ; 26.477,46.416 26.477,46.924 ; 26.477,46.416 26.985,46.416 ; 26.477,46.924 26.477,47.432 ; 26.477,46.924 26.985,46.924 ; 26.477,47.432 26.477,47.94 ; 26.477,47.432 26.985,47.432 ; 26.477,47.94 26.477,48.448 ; 26.477,47.94 26.985,47.94 ; 26.477,48.448 26.477,48.956 ; 26.477,48.448 26.985,48.448 ; 26.477,48.956 26.477,49.464 ; 26.477,48.956 26.985,48.956 ; 26.477,49.464 26.477,49.972 ; 26.477,49.464 26.985,49.464 ; 26.477,49.972 26.477,50.48 ; 26.477,49.972 26.985,49.972 ; 26.477,50.48 26.477,50.988 ; 26.477,50.48 26.985,50.48 ; 26.477,50.988 26.477,51.496 ; 26.477,50.988 pad.@26.985,50.988 ; 26.477,51.496 26.477,52.004 ; 26.477,51.496 26.985,51.496 ; 26.477,52.004 26.477,52.512 ; 26.477,52.004 26.985,52.004 ; 26.477,52.512 26.477,53.02 ; 26.477,52.512 26.985,52.512 ; 26.477,53.02 26.477,53.528 ; 26.477,53.02 26.985,53.02 ; 26.477,53.528 26.985,53.528 ; 26.477,53.528 26.477,54.036 ; 26.477,54.036 26.985,54.036 ; 26.477,54.036 26.477,54.544 ; 26.477,54.544 26.477,55.052 ; 26.477,54.544 26.985,54.544 ; 26.477,55.052 26.985,55.052 ; 26.477,55.052 26.477,55.56 ; 26.477,55.56 26.477,56.068 ; 26.477,55.56 26.985,55.56 ; 26.477,56.068 26.985,56.068 ; 26.477,56.068 26.477,56.178 ; 26.477,56.178 26.985,56.177 ; 26.604,25.588 26.985,25.588 ; 26.604,25.588 26.858,25.334 26.858,25.08 ; 26.858,21.016 26.985,21.016 ; 26.858,21.016 26.858,21.524 ; 26.858,21.016 26.858,20.889 26.985,20.889 ; 26.858,21.524 26.985,21.524 ; 26.858,21.524 26.858,22.032 ; 26.858,22.032 26.985,22.032 ; 26.858,22.032 26.858,22.54 ; 26.858,22.54 26.985,22.54 ; 26.858,22.54 26.858,23.048 ; 26.858,23.048 26.985,23.048 ; 26.858,23.048 26.858,23.556 ; 26.858,23.556 26.985,23.556 ; 26.858,23.556 26.858,24.064 ; 26.858,24.064 26.985,24.064 ; 26.858,24.064 26.858,24.572 ; 26.858,24.572 26.985,24.572 ; 26.858,24.572 26.858,25.08 ; 26.858,25.08 26.985,25.08 ; 26.985,20.889 26.985,21.016 ; 26.985,20.889 27.493,20.889 ; 26.985,21.016 27.493,21.016 ; 26.985,21.016 26.985,21.524 ; 26.985,21.524 26.985,22.032 ; 26.985,21.524 pad.@27.493,21.524 ; 26.985,22.032 26.985,22.54 ; 26.985,22.032 27.493,22.032 ; 26.985,22.54 26.985,23.048 ; 26.985,22.54 27.493,22.54 ; 26.985,23.048 26.985,23.556 ; 26.985,23.048 27.493,23.048 ; 26.985,23.556 26.985,24.064 ; 26.985,23.556 27.493,23.556 ; 26.985,24.064 26.985,24.572 ; 26.985,24.064 27.493,24.064 ; 26.985,24.572 26.985,25.08 ; 26.985,24.572 27.493,24.572 ; 26.985,25.08 26.985,25.588 ; 26.985,25.08 27.493,25.08 ; 26.985,25.588 26.985,26.096 ; 26.985,25.588 27.493,25.588 ; 26.985,26.096 26.985,26.604 ; 26.985,26.096 27.493,26.096 ; 26.985,26.604 27.493,26.604 ; 26.985,26.604 26.985,27.112 ; 26.985,27.112 26.985,27.62 ; 26.985,27.112 27.493,27.112 ; 26.985,27.62 26.985,28.128 ; 26.985,27.62 27.493,27.62 ; 26.985,28.128 26.985,28.636 ; 26.985,28.128 27.493,28.128 ; 26.985,28.636 26.985,29.144 ; 26.985,28.636 27.493,28.636 ; 26.985,29.144 26.985,29.652 ; 26.985,29.144 27.493,29.144 ; 26.985,29.652 26.985,30.16 ; 26.985,29.652 27.493,29.652 ; 26.985,30.16 26.985,30.668 ; 26.985,30.16 27.493,30.16 ; 26.985,30.668 26.985,31.176 ; 26.985,30.668 27.493,30.668 ; 26.985,31.176 26.985,31.684 ; 26.985,31.176 27.493,31.176 ; 26.985,31.684 26.985,32.192 ; 26.985,31.684 27.493,31.684 ; 26.985,32.192 26.985,32.7 ; 26.985,32.192 27.493,32.192 ; 26.985,32.7 26.985,33.208 ; 26.985,32.7 27.493,32.7 ; 26.985,33.208 26.985,33.716 ; 26.985,33.208 27.493,33.208 ; 26.985,33.716 26.985,34.224 ; 26.985,33.716 27.493,33.716 ; 26.985,34.224 26.985,34.732 ; 26.985,34.224 27.493,34.224 ; 26.985,34.732 27.493,34.732 ; 26.985,34.732 26.985,35.24 ; 26.985,35.24 27.493,35.24 ; 26.985,35.24 26.985,35.748 ; 26.985,35.748 27.493,35.748 ; 26.985,35.748 26.985,36.256 ; 26.985,36.256 27.493,36.256 ; 26.985,36.256 26.985,36.764 ; 26.985,36.764 26.985,37.272 ; 26.985,36.764 27.493,36.764 ; 26.985,37.272 26.985,37.78 ; 26.985,37.272 27.493,37.272 ; 26.985,37.78 26.985,38.288 ; 26.985,37.78 27.493,37.78 ; 26.985,38.288 26.985,38.796 ; 26.985,38.288 27.493,38.288 ; 26.985,38.796 26.985,39.304 ; 26.985,38.796 27.493,38.796 ; 26.985,39.304 26.985,39.812 ; 26.985,39.304 27.493,39.304 ; 26.985,39.812 27.493,39.812 ; 26.985,39.812 26.985,40.32 ; 26.985,40.32 26.985,40.828 ; 26.985,40.32 27.366,40.32 ; 26.985,40.828 27.276,40.828 ; 26.985,40.828 26.985,41.336 ; 26.985,41.336 26.985,41.844 ; 26.985,41.336 27.276,41.336 ; 26.985,41.844 26.985,42.352 ; 26.985,41.844 27.276,41.844 ; 26.985,42.352 26.985,42.86 ; 26.985,42.352 27.276,42.352 ; 26.985,42.86 26.985,43.368 ; 26.985,42.86 27.276,42.86 ; 26.985,43.368 26.985,43.876 ; 26.985,43.368 27.276,43.368 ; 26.985,43.876 26.985,44.384 ; 26.985,43.876 27.276,43.876 ; 26.985,44.384 26.985,44.892 ; 26.985,44.384 27.276,44.384 ; 26.985,44.892 26.985,45.4 ; 26.985,44.892 27.276,44.892 ; 26.985,45.4 26.985,45.908 ; 26.985,45.4 27.276,45.4 ; 26.985,45.908 26.985,46.416 ; 26.985,45.908 27.276,45.908 ; 26.985,46.416 26.985,46.924 ; 26.985,46.416 27.276,46.416 ; 26.985,46.924 26.985,47.432 ; 26.985,46.924 27.276,46.924 ; 26.985,47.432 26.985,47.94 ; 26.985,47.432 27.276,47.432 ; 26.985,47.94 26.985,48.448 ; 26.985,47.94 27.276,47.94 ; 26.985,48.448 26.985,48.956 ; 26.985,48.448 27.276,48.448 ; 26.985,48.956 26.985,49.464 ; 26.985,48.956 27.276,48.956 ; 26.985,49.464 26.985,49.972 ; 26.985,49.464 27.276,49.464 ; 26.985,49.972 26.985,50.48 ; 26.985,49.972 27.276,49.972 ; 26.985,50.48 pad.@26.985,50.988 ; 26.985,50.48 27.276,50.48 ; pad.@26.985,50.988 pad.@27.276,50.988 ; pad.@26.985,50.988 26.985,51.496 ; 26.985,51.496 26.985,52.004 ; 26.985,51.496 27.276,51.496 ; 26.985,52.004 26.985,52.512 ; 26.985,52.004 27.276,52.004 ; 26.985,52.512 26.985,53.02 ; 26.985,52.512 27.276,52.512 ; 26.985,53.02 26.985,53.528 ; 26.985,53.02 27.276,53.02 ; 26.985,53.528 26.985,54.036 ; 26.985,53.528 27.276,53.528 ; 26.985,54.036 26.985,54.544 ; 26.985,54.036 27.445,54.036 ; 26.985,54.544 26.985,55.052 ; 26.985,54.544 27.493,54.544 ; 26.985,55.052 27.493,55.052 ; 26.985,55.052 26.985,55.56 ; 26.985,55.56 26.985,56.068 ; 26.985,55.56 pad.@27.493,55.56 ; 26.985,56.068 27.493,56.068 ; 26.985,56.068 26.985,56.177 ; 26.985,56.177 27.493,56.175 ; 27.276,40.701 ccw(c28.128,40.701) 27.366,40.32 ; 27.276,40.701 ccw(c28.128,40.701) 27.366,40.32 ; 27.276,40.701 27.276,40.828 ; 27.276,40.828 27.276,41.336 ; 27.276,41.336 27.276,41.844 ; 27.276,41.844 27.276,42.352 ; 27.276,42.352 27.276,42.86 ; 27.276,42.86 27.276,43.368 ; 27.276,43.368 27.276,43.876 ; 27.276,43.876 27.276,44.384 ; 27.276,44.384 27.276,44.892 ; 27.276,44.892 27.276,45.4 ; 27.276,45.4 27.276,45.908 ; 27.276,45.908 27.276,46.416 ; 27.276,46.416 27.276,46.924 ; 27.276,46.924 27.276,47.432 ; 27.276,47.432 27.276,47.94 ; 27.276,47.94 27.276,48.448 ; 27.276,48.448 27.276,48.956 ; 27.276,48.956 27.276,49.464 ; 27.276,49.464 27.276,49.972 ; 27.276,49.972 27.276,50.48 ; 27.276,50.48 pad.@27.276,50.988 ; pad.@27.276,50.988 27.276,51.496 ; 27.276,51.496 27.276,52.004 ; 27.276,52.004 27.276,52.512 ; 27.276,52.512 27.276,53.02 ; 27.276,53.02 27.276,53.528 ; 27.276,53.528 cw(c28.128,53.528) 27.445,54.036 ; 27.276,53.528 cw(c28.128,53.528) 27.445,54.036 ; 27.366,40.32 ccw(c28.128,40.701) 27.369,40.314 ; 27.366,40.32 ccw(c28.128,40.701) 27.369,40.314 ; 27.369,40.314 ccw(c28.128,40.701) 27.493,40.134 ; 27.369,40.314 ccw(c28.128,40.701) 27.493,40.134 ; 27.445,54.036 cw(c28.128,53.528) 27.493,54.095 ; 27.445,54.036 cw(c28.128,53.528) 27.493,54.095 ; 27.493,20.889 27.493,21.016 ; 27.493,20.889 28.001,20.889 ; 27.493,21.016 pad.@27.493,21.524 ; 27.493,21.016 28.001,21.016 ; pad.@27.493,21.524 27.493,22.032 ; pad.@27.493,21.524 pad.@28.001,21.524 ; 27.493,22.032 27.493,22.54 ; 27.493,22.032 28.001,22.032 ; 27.493,22.54 27.493,23.048 ; 27.493,22.54 28.001,22.54 ; 27.493,23.048 27.493,23.556 ; 27.493,23.048 28.001,23.048 ; 27.493,23.556 27.493,24.064 ; 27.493,23.556 28.001,23.556 ; 27.493,24.064 27.493,24.572 ; 27.493,24.064 28.001,24.064 ; 27.493,24.572 27.493,25.08 ; 27.493,24.572 28.001,24.572 ; 27.493,25.08 27.493,25.588 ; 27.493,25.08 28.001,25.08 ; 27.493,25.588 27.493,26.096 ; 27.493,25.588 28.001,25.588 ; 27.493,26.096 27.493,26.604 ; 27.493,26.096 28.001,26.096 ; 27.493,26.604 28.001,26.604 ; 27.493,26.604 27.493,27.112 ; 27.493,27.112 27.493,27.62 ; 27.493,27.112 28.001,27.112 ; 27.493,27.62 27.493,28.128 ; 27.493,27.62 28.001,27.62 ; 27.493,28.128 27.493,28.636 ; 27.493,28.128 28.001,28.128 ; 27.493,28.636 27.493,29.144 ; 27.493,28.636 28.001,28.636 ; 27.493,29.144 27.493,29.652 ; 27.493,29.144 28.001,29.144 ; 27.493,29.652 27.493,30.16 ; 27.493,29.652 28.001,29.652 ; 27.493,30.16 27.493,30.668 ; 27.493,30.16 28.001,30.16 ; 27.493,30.668 27.493,31.176 ; 27.493,30.668 28.001,30.668 ; 27.493,31.176 27.493,31.684 ; 27.493,31.176 28.001,31.176 ; 27.493,31.684 27.493,32.192 ; 27.493,31.684 28.001,31.684 ; 27.493,32.192 27.493,32.7 ; 27.493,32.192 28.001,32.192 ; 27.493,32.7 27.493,33.208 ; 27.493,32.7 28.001,32.7 ; 27.493,33.208 27.493,33.716 ; 27.493,33.208 28.001,33.208 ; 27.493,33.716 27.493,34.224 ; 27.493,33.716 28.001,33.716 ; 27.493,34.224 27.493,34.732 ; 27.493,34.224 28.001,34.224 ; 27.493,34.732 28.001,34.732 ; 27.493,34.732 27.493,35.24 ; 27.493,35.24 28.001,35.24 ; 27.493,35.24 27.493,35.748 ; 27.493,35.748 28.001,35.748 ; 27.493,35.748 27.493,36.256 ; 27.493,36.256 28.001,36.256 ; 27.493,36.256 27.493,36.764 ; 27.493,36.764 27.493,37.272 ; 27.493,36.764 28.001,36.764 ; 27.493,37.272 27.493,37.78 ; 27.493,37.272 27.73,37.272 ; 27.493,37.78 27.493,38.288 ; 27.493,38.288 27.493,38.796 ; 27.493,38.288 27.886,38.288 ; 27.493,38.796 27.493,39.304 ; 27.493,38.796 28.001,38.796 ; 27.493,39.304 27.493,39.812 ; 27.493,39.304 28.001,39.304 ; 27.493,39.812 27.73,39.812 ; 27.493,39.812 27.493,40.134 ; 27.493,40.134 ccw(c28.128,40.701) 27.527,40.098 ; 27.493,54.095 cw(c28.128,53.528) 27.526,54.13 ccw(c28.128,53.528) 27.493,54.095 ; 27.493,54.095 27.493,54.544 ; 27.493,54.544 27.493,55.052 ; 27.493,54.544 27.94,54.544 ; 27.493,55.052 28.001,55.052 ; 27.493,55.052 pad.@27.493,55.56 ; pad.@27.493,55.56 27.493,56.068 ; pad.@27.493,55.56 pad.@28.001,55.56 ; 27.493,56.068 27.493,56.175 ; 27.493,56.068 28.001,56.068 ; 27.493,56.175 28.001,56.173 ; 27.528,40.097 27.687,39.937 ; 27.687,39.937 ccw(c28.636,40.193) 27.73,39.812 ; 27.73,37.272 ccw(c28.636,37.653) 27.732,37.269 ccw(c28.636,37.653) 28.001,36.903 ; 27.73,39.812 ccw(c28.636,40.193) 28.001,39.443 ; 27.886,38.288 cw(c28.636,37.653) 28.001,38.403 ; 27.94,54.544 28.001,54.605 ; 28.001,20.889 28.001,21.016 ; 28.001,20.889 28.509,20.889 ; 28.001,21.016 28.509,21.016 ; 28.001,21.016 pad.@28.001,21.524 ; pad.@28.001,21.524 28.001,22.032 ; pad.@28.001,21.524 28.509,21.524 ; 28.001,22.032 28.001,22.54 ; 28.001,22.032 28.509,22.032 ; 28.001,22.54 28.001,23.048 ; 28.001,22.54 28.509,22.54 ; 28.001,23.048 28.001,23.556 ; 28.001,23.048 28.509,23.048 ; 28.001,23.556 28.001,24.064 ; 28.001,23.556 28.507,23.556 ; 28.001,24.064 28.001,24.572 ; 28.001,24.064 28.228,24.064 ; 28.001,24.572 28.001,25.08 ; 28.001,24.572 28.179,24.572 ; 28.001,25.08 28.001,25.588 ; 28.001,25.588 28.001,26.096 ; 28.001,25.588 28.509,25.588 ; 28.001,26.096 28.001,26.604 ; 28.001,26.096 28.509,26.096 ; 28.001,26.604 28.001,27.112 ; 28.001,26.604 28.509,26.604 ; 28.001,27.112 28.001,27.62 ; 28.001,27.112 28.509,27.112 ; 28.001,27.62 28.001,28.128 ; 28.001,27.62 28.509,27.62 ; 28.001,28.128 28.001,28.636 ; 28.001,28.128 28.509,28.128 ; 28.001,28.636 28.001,29.144 ; 28.001,28.636 28.509,28.636 ; 28.001,29.144 28.001,29.652 ; 28.001,29.144 28.509,29.144 ; 28.001,29.652 28.001,30.16 ; 28.001,29.652 28.509,29.652 ; 28.001,30.16 28.001,30.668 ; 28.001,30.16 28.509,30.16 ; 28.001,30.668 28.001,31.176 ; 28.001,30.668 28.509,30.668 ; 28.001,31.176 28.001,31.684 ; 28.001,31.176 28.509,31.176 ; 28.001,31.684 28.001,32.192 ; 28.001,31.684 28.509,31.684 ; 28.001,32.192 28.001,32.7 ; 28.001,32.192 28.509,32.192 ; 28.001,32.7 28.001,33.208 ; 28.001,32.7 28.509,32.7 ; 28.001,33.208 28.001,33.716 ; 28.001,33.208 28.509,33.208 ; 28.001,33.716 28.001,34.224 ; 28.001,33.716 28.509,33.716 ; 28.001,34.224 28.001,34.732 ; 28.001,34.224 28.509,34.224 ; 28.001,34.732 28.001,35.24 ; 28.001,34.732 28.509,34.732 ; 28.001,35.24 28.001,35.748 ; 28.001,35.24 28.509,35.24 ; 28.001,35.748 28.001,36.256 ; 28.001,35.748 28.509,35.748 ; 28.001,36.256 28.001,36.764 ; 28.001,36.256 28.509,36.256 ; 28.001,36.764 28.001,36.903 ; 28.001,36.764 28.217,36.764 ; 28.001,36.903 ccw(c28.636,37.653) 28.004,36.9 ccw(c28.636,37.653) 28.217,36.764 ; 28.001,38.403 cw(c28.636,37.653) 28.004,38.406 cw(c28.636,37.653) 28.38,38.602 ; 28.001,38.403 28.001,38.796 ; 28.001,38.796 28.509,38.796 ; 28.001,38.796 28.001,39.304 ; 28.001,39.304 28.001,39.443 ; 28.001,39.304 28.217,39.304 ; 28.001,39.443 ccw(c28.636,40.193) 28.004,39.44 ccw(c28.636,40.193) 28.217,39.304 ; 28.001,54.605 28.448,55.052 ; 28.001,54.605 28.001,55.052 ; 28.001,55.052 pad.@28.001,55.56 ; 28.001,55.052 28.448,55.052 ; pad.@28.001,55.56 28.509,55.56 ; pad.@28.001,55.56 28.001,56.068 ; 28.001,56.068 28.509,56.068 ; 28.001,56.068 28.001,56.173 ; 28.001,56.173 29.017,56.17 ; 28.179,24.572 ccw(c29.525,24.445) 28.173,24.445 ccw(c29.525,24.445) 28.226,24.072 ccw(c29.525,24.445) 28.228,24.064 ; 28.217,36.764 ccw(c28.636,37.653) 28.221,36.762 ccw(c28.636,37.653) 28.509,36.679 ; 28.217,39.304 ccw(c28.636,40.193) 28.221,39.302 ccw(c28.636,40.193) 28.509,39.219 ; 28.228,24.064 ccw(c29.525,24.445) 28.505,23.558 ccw(c29.525,24.445) 28.507,23.556 ; 28.448,55.052 28.509,55.113 ; 28.507,23.556 ccw(c29.525,24.445) 28.509,23.554 ; 28.509,20.889 28.509,21.016 ; 28.509,20.889 29.017,20.889 ; 28.509,21.016 28.509,21.524 ; 28.509,21.016 29.017,21.016 ; 28.509,21.524 28.509,22.032 ; 28.509,21.524 29.017,21.524 ; 28.509,22.032 28.509,22.54 ; 28.509,22.032 29.017,22.032 ; 28.509,22.54 28.509,23.048 ; 28.509,22.54 29.017,22.54 ; 28.509,23.048 29.017,23.048 ; 28.509,23.048 28.509,23.554 ; 28.509,23.554 ccw(c29.525,24.445) 29.017,23.193 ; 28.509,25.588 28.509,26.096 ; 28.509,25.588 28.804,25.588 ; 28.509,26.096 28.509,26.604 ; 28.509,26.096 29.017,26.096 ; 28.509,26.604 28.509,27.112 ; 28.509,26.604 29.017,26.604 ; 28.509,27.112 28.509,27.62 ; 28.509,27.112 29.017,27.112 ; 28.509,27.62 28.509,28.128 ; 28.509,27.62 29.017,27.62 ; 28.509,28.128 28.509,28.636 ; 28.509,28.128 29.017,28.128 ; 28.509,28.636 28.509,29.144 ; 28.509,28.636 29.017,28.636 ; 28.509,29.144 28.509,29.652 ; 28.509,29.144 29.017,29.144 ; 28.509,29.652 28.509,30.16 ; 28.509,29.652 29.017,29.652 ; 28.509,30.16 28.509,30.668 ; 28.509,30.16 29.017,30.16 ; 28.509,30.668 28.509,31.176 ; 28.509,30.668 29.017,30.668 ; 28.509,31.176 28.509,31.684 ; 28.509,31.176 29.017,31.176 ; 28.509,31.684 28.509,32.192 ; 28.509,31.684 29.017,31.684 ; 28.509,32.192 28.509,32.7 ; 28.509,32.192 29.017,32.192 ; 28.509,32.7 28.509,33.208 ; 28.509,32.7 29.017,32.7 ; 28.509,33.208 28.509,33.716 ; 28.509,33.208 29.017,33.208 ; 28.509,33.716 28.509,34.224 ; 28.509,33.716 29.017,33.716 ; 28.509,34.224 28.509,34.732 ; 28.509,34.224 29.017,34.224 ; 28.509,34.732 28.509,35.24 ; 28.509,34.732 29.017,34.732 ; 28.509,35.24 28.509,35.748 ; 28.509,35.24 29.017,35.24 ; 28.509,35.748 28.509,36.256 ; 28.509,35.748 29.017,35.748 ; 28.509,36.256 29.017,36.256 ; 28.509,36.256 28.509,36.679 ; 28.509,36.679 ccw(c28.636,37.653) 28.516,36.678 ccw(c28.636,37.653) 29.017,36.747 ; 28.509,38.796 28.509,39.219 ; 28.509,55.113 28.509,55.56 ; 28.509,55.113 28.956,55.56 ; 28.509,55.56 28.509,56.068 ; 28.509,55.56 28.956,55.56 ; 28.509,56.068 29.017,56.068 ; 28.804,25.588 cw(c29.525,24.445) 28.809,25.591 cw(c29.525,24.445) 29.017,25.697 ; 28.956,55.56 29.017,55.621 ; 29.017,20.889 29.017,21.016 ; 29.017,20.889 29.525,20.889 ; 29.017,21.016 29.017,21.524 ; 29.017,21.016 29.525,21.016 ; 29.017,21.524 29.017,22.032 ; 29.017,21.524 29.525,21.524 ; 29.017,22.032 29.017,22.54 ; 29.017,22.032 29.525,22.032 ; 29.017,22.54 29.017,23.048 ; 29.017,22.54 29.525,22.54 ; 29.017,23.048 29.525,23.048 ; 29.017,23.048 29.017,23.193 ; 29.017,23.193 ccw(c29.525,24.445) 29.019,23.192 ccw(c29.525,24.445) 29.525,23.093 ; 29.017,25.697 cw(c29.525,24.445) 29.019,25.698 cw(c29.525,24.445) 29.525,25.797 ; 29.017,25.698 29.017,26.096 ; 29.017,26.096 29.017,26.604 ; 29.017,26.096 29.525,26.096 ; 29.017,26.604 29.525,26.604 ; 29.017,26.604 29.017,27.112 ; 29.017,27.112 29.017,27.62 ; 29.017,27.112 29.525,27.112 ; 29.017,27.62 29.017,28.128 ; 29.017,27.62 29.525,27.62 ; 29.017,28.128 29.017,28.636 ; 29.017,28.128 29.525,28.128 ; 29.017,28.636 29.017,29.144 ; 29.017,28.636 29.525,28.636 ; 29.017,29.144 29.017,29.652 ; 29.017,29.144 29.525,29.144 ; 29.017,29.652 29.017,30.16 ; 29.017,29.652 29.525,29.652 ; 29.017,30.16 29.017,30.668 ; 29.017,30.16 29.525,30.16 ; 29.017,30.668 29.017,31.176 ; 29.017,30.668 29.525,30.668 ; 29.017,31.176 29.017,31.684 ; 29.017,31.176 29.525,31.176 ; 29.017,31.684 29.017,32.192 ; 29.017,31.684 29.525,31.684 ; 29.017,32.192 29.525,32.192 ; 29.017,32.192 29.017,32.7 ; 29.017,32.7 29.017,33.208 ; 29.017,32.7 29.525,32.7 ; 29.017,33.208 29.017,33.716 ; 29.017,33.208 29.525,33.208 ; 29.017,33.716 29.017,34.224 ; 29.017,33.716 29.525,33.716 ; 29.017,34.224 29.017,34.732 ; 29.017,34.224 29.525,34.224 ; 29.017,34.732 29.525,34.732 ; 29.017,34.732 29.017,35.24 ; 29.017,35.24 29.525,35.24 ; 29.017,35.24 29.017,35.748 ; 29.017,35.748 29.525,35.748 ; 29.017,35.748 29.017,36.256 ; 29.017,36.256 29.525,36.256 ; 29.017,36.256 29.017,36.747 ; 29.017,36.747 ccw(c28.636,37.653) 29.055,36.764 ; 29.017,55.621 29.564,56.168 29.017,56.17 ; 29.017,55.621 29.017,56.068 ; 29.017,56.068 29.017,56.17 ; 29.055,36.764 ccw(c28.636,37.653) 29.525,37.234 ; 29.055,36.764 29.525,36.764 ; 29.525,20.889 29.525,21.016 ; 29.525,20.889 30.033,20.889 ; 29.525,21.016 29.525,21.524 ; 29.525,21.016 30.033,21.016 ; 29.525,21.524 29.525,22.032 ; 29.525,21.524 30.033,21.524 ; 29.525,22.032 29.525,22.54 ; 29.525,22.032 30.033,22.032 ; 29.525,22.54 29.525,23.048 ; 29.525,22.54 30.033,22.54 ; 29.525,23.048 30.033,23.048 ; 29.525,23.048 29.525,23.093 ; 29.525,23.093 ccw(c29.525,24.445) 30.031,23.192 ccw(c29.525,24.445) 30.033,23.192 ; 29.525,25.797 cw(c29.525,24.445) 30.031,25.698 cw(c29.525,24.445) 30.033,25.698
